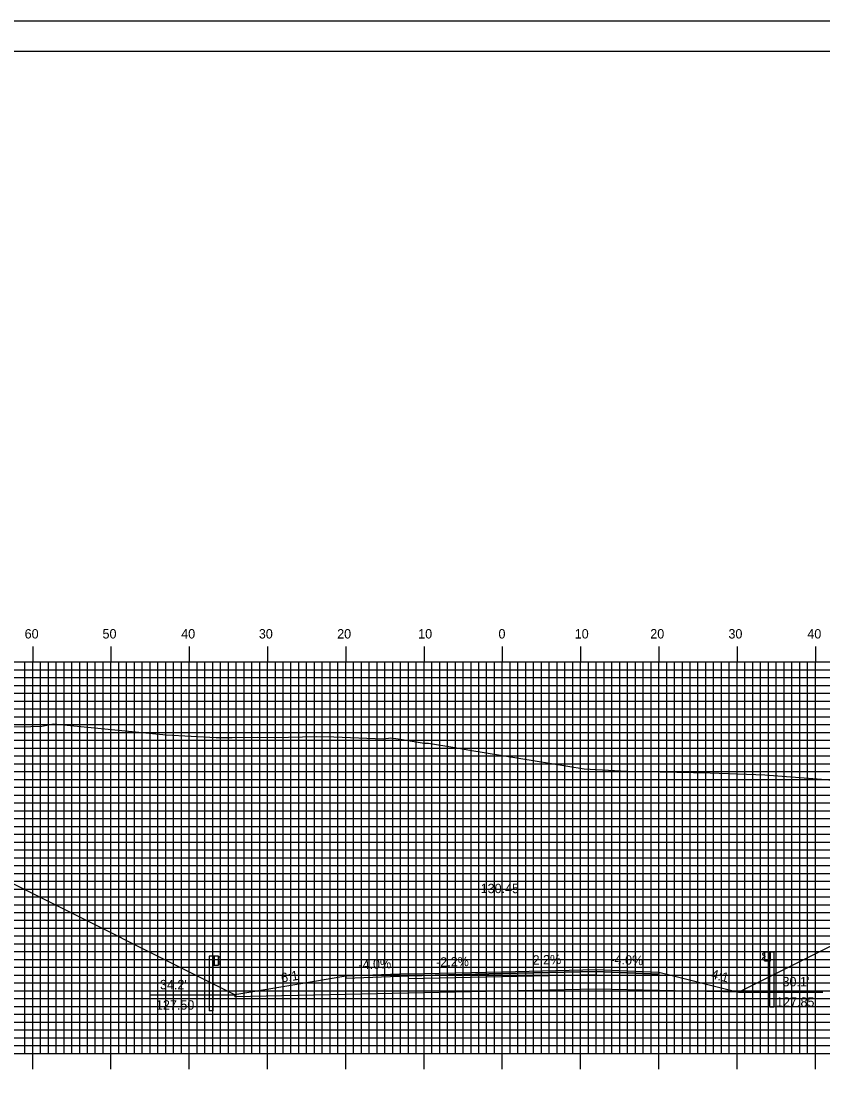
# Model space of a CAD drawing. Extents: x 1785008 to 1785352, y 442591 to 442811.
# Drawn here: x 1785112.5 to 1785215, y 442676.2 to 442810.5 of the extents above; entities that cross this region are included whole.
import ezdxf

# ---------------------------------------------------------------- set-up
doc = ezdxf.new("R2010")
doc.units = 0
for name, color, linetype in [('ANNOTATION', 7, 'Continuous'), ('BORDER', 7, 'Continuous'), ('D_Guardrail_Beam_Lt', 7, 'Continuous'), ('D_Guardrail_Beam_Rt', 7, 'Continuous'), ('D_Roadway_Centerline', 7, 'Continuous'), ('D_Roadway_Centerline_Text', 7, 'Continuous'), ('D_Roadway_Edge_Shoulder', 7, 'Continuous'), ('D_Roadway_Edge_TW', 7, 'Continuous'), ('D_Roadway_Pavement', 7, 'Continuous'), ('D_Roadway_SlopeLines', 7, 'Continuous'), ('D_Roadway_SubGrade', 7, 'Continuous'), ('H_V ANNOTATION', 7, 'Continuous'), ('MAJOR', 7, 'Continuous'), ('MINOR', 7, 'Continuous'), ('PDRAIN', 7, 'Continuous'), ('PLOT BOUNDARY', 7, 'Continuous'), ('S_Roadway_Centerline', 7, 'Continuous')]:
    doc.layers.add(name, color=color, linetype=linetype)

msp = doc.modelspace()

# ---------------------------------------------------------------- linework, layer by layer
at = {"layer": 'BORDER'}
msp.add_lwpolyline([(1785024.43, 442596.67), (1785344.43, 442596.67), (1785344.43, 442806.67), (1785024.43, 442806.67)], close=True, dxfattribs=at)
at = {"layer": 'D_Guardrail_Beam_Lt'}
for p, q in [((1785136.59, 442691.11), (1785136.59, 442684.11)), ((1785137.06, 442691.11), (1785136.59, 442691.11)), ((1785137.75, 442691.11), (1785137.06, 442691.11)), ((1785137.06, 442691.11), (1785137.06, 442689.94)), ((1785137.12, 442691.11), (1785137.12, 442689.94)), ((1785137.23, 442691.11), (1785137.23, 442689.94)), ((1785137.75, 442689.94), (1785137.75, 442691.11)), ((1785137.75, 442691.03), (1785137.82, 442691.01)), ((1785137.84, 442691.01), (1785137.98, 442690.91)), ((1785137.06, 442689.94), (1785137.75, 442689.94)), ((1785137.08, 442684.11), (1785137.08, 442689.94)), ((1785137.75, 442690.56), (1785137.75, 442690.49)), ((1785137.82, 442690.04), (1785137.75, 442690.03)), ((1785137.98, 442690.76), (1785137.79, 442690.63)), ((1785137.79, 442690.43), (1785137.98, 442690.29)), ((1785137.98, 442690.15), (1785137.84, 442690.05)), ((1785137.08, 442684.11), (1785136.59, 442684.11))]:
    msp.add_line(p, q, dxfattribs=at)
for centre, major_axis, start_param, end_param in [((1785137.81, 442690.97), (0.0417, 0), 0.959931, 1.376053), ((1785137.83, 442690.56), (-0.0789, 0), 5.323254, 6.283185), ((1785137.83, 442690.49), (-0.0789, 0), 6.283185, 7.243116), ((1785137.81, 442690.08), (0.0417, 0), 4.907132, 5.323254), ((1785137.93, 442690.83), (0.0877, 0), 5.323254, 7.243116), ((1785137.93, 442690.22), (0.0877, 0), 5.323254, 7.243116)]:
    msp.add_ellipse(centre, major_axis=major_axis, ratio=0.995501, start_param=start_param, end_param=end_param, dxfattribs=at)
at = {"layer": 'D_Guardrail_Beam_Rt'}
for p, q in [((1785207.47, 442691.53), (1785207.32, 442691.43)), ((1785207.32, 442691.29), (1785207.52, 442691.15)), ((1785207.56, 442691.55), (1785207.48, 442691.54)), ((1785207.55, 442691.09), (1785207.55, 442691.02)), ((1785207.56, 442691.64), (1785208.24, 442691.64)), ((1785207.56, 442690.47), (1785207.56, 442691.64)), ((1785208.08, 442691.64), (1785208.08, 442690.47)), ((1785208.18, 442691.64), (1785208.18, 442690.47)), ((1785208.24, 442691.64), (1785208.71, 442691.64)), ((1785208.24, 442691.64), (1785208.24, 442690.47)), ((1785208.71, 442691.64), (1785208.71, 442684.64)), ((1785207.52, 442690.95), (1785207.32, 442690.82)), ((1785207.32, 442690.68), (1785207.47, 442690.58)), ((1785207.48, 442690.57), (1785207.56, 442690.55)), ((1785208.24, 442690.47), (1785207.56, 442690.47)), ((1785208.22, 442684.64), (1785208.22, 442690.47)), ((1785208.22, 442684.64), (1785208.71, 442684.64))]:
    msp.add_line(p, q, dxfattribs=at)
for centre, major_axis, start_param, end_param in [((1785207.37, 442691.36), (-0.0877, 0), 5.323254, 7.243116), ((1785207.49, 442691.5), (-0.0417, 0), 4.907132, 5.323254), ((1785207.47, 442691.09), (0.0789, 0), 0, 0.959931), ((1785207.47, 442691.02), (0.0789, 0), 5.323254, 6.283185), ((1785207.37, 442690.75), (-0.0877, 0), 5.323254, 7.243116), ((1785207.49, 442690.61), (-0.0417, 0), 0.959931, 1.376053)]:
    msp.add_ellipse(centre, major_axis=major_axis, ratio=0.995501, start_param=start_param, end_param=end_param, dxfattribs=at)
at = {"layer": 'D_Roadway_Edge_Shoulder'}
for points in [[(1785162.03, 442688.85), (1785154.03, 442688.53), (1785154.03, 442688.28), (1785162.03, 442688.6)], [(1785186.03, 442689.37), (1785194.03, 442689.05), (1785194.03, 442688.8), (1785186.03, 442689.12)]]:
    msp.add_lwpolyline(points, close=True, dxfattribs=at)
at = {"layer": 'D_Roadway_Edge_TW'}
msp.add_lwpolyline([(1785162.03, 442688.6), (1785162.03, 442688.85), (1785174.03, 442689.11), (1785186.03, 442689.37), (1785186.03, 442689.12), (1785174.03, 442688.86)], close=True, dxfattribs=at)
at = {"layer": 'D_Roadway_Pavement'}
msp.add_lwpolyline([(1785162.03, 442688.18), (1785162.03, 442688.6), (1785174.03, 442688.86), (1785186.03, 442689.12), (1785186.03, 442688.71), (1785174.03, 442688.44)], close=True, dxfattribs=at)
at = {"layer": 'D_Roadway_SlopeLines'}
for p in [(1785139.85, 442686.16), (1785143.85, 442685.98)]:
    msp.add_line(p, (1785139.85, 442685.9), dxfattribs=at)
for points in [[(1785139.85, 442686.16), (1785082.14, 442715.02), (1785080.89, 442715.56), (1785079.64, 442715.93), (1785078.39, 442716.14), (1785077.14, 442716.18)], [(1785204.2, 442686.51), (1785248.83, 442708.82), (1785250.08, 442709.36), (1785251.33, 442709.73), (1785252.58, 442709.92), (1785253.83, 442709.94)], [(1785154.03, 442688.53), (1785148.03, 442687.53), (1785139.85, 442686.16)], [(1785194.03, 442689.05), (1785204.2, 442686.51)]]:
    msp.add_lwpolyline(points, dxfattribs=at)
at = {"layer": 'D_Roadway_SubGrade'}
msp.add_lwpolyline([(1785154.03, 442688.53), (1785154.03, 442688.28), (1785162.03, 442688.6), (1785174.03, 442688.86), (1785186.03, 442689.12), (1785194.03, 442688.8), (1785194.03, 442689.05), (1785204.2, 442686.51), (1785186.03, 442686.87), (1785174.03, 442686.61), (1785162.03, 442686.35), (1785143.85, 442685.98)], dxfattribs=at)
at = {"layer": 'MAJOR'}
for p, q in [((1785114.03, 442730.67), (1785114.03, 442728.67)), ((1785124.03, 442730.67), (1785124.03, 442728.67)), ((1785134.03, 442730.67), (1785134.03, 442728.67)), ((1785144.03, 442730.67), (1785144.03, 442728.67)), ((1785154.03, 442730.67), (1785154.03, 442728.67)), ((1785164.03, 442730.67), (1785164.03, 442728.67)), ((1785174.03, 442730.67), (1785174.03, 442728.67)), ((1785184.03, 442730.67), (1785184.03, 442728.67)), ((1785194.03, 442730.67), (1785194.03, 442728.67)), ((1785204.03, 442730.67), (1785204.03, 442728.67)), ((1785214.03, 442730.67), (1785214.03, 442728.67)), ((1785034.03, 442728.67), (1785314.03, 442728.67)), ((1785034.03, 442728.67), (1785314.03, 442728.67)), ((1785114.03, 442678.67), (1785114.03, 442728.67)), ((1785124.03, 442678.67), (1785124.03, 442728.67)), ((1785134.03, 442678.67), (1785134.03, 442728.67)), ((1785144.03, 442678.67), (1785144.03, 442728.67)), ((1785154.03, 442678.67), (1785154.03, 442728.67)), ((1785164.03, 442678.67), (1785164.03, 442728.67)), ((1785174.03, 442678.67), (1785174.03, 442728.67)), ((1785184.03, 442678.67), (1785184.03, 442728.67)), ((1785194.03, 442678.67), (1785194.03, 442728.67)), ((1785204.03, 442678.67), (1785204.03, 442728.67)), ((1785214.03, 442678.67), (1785214.03, 442728.67)), ((1785034.03, 442723.67), (1785314.03, 442723.67)), ((1785034.03, 442718.67), (1785314.03, 442718.67)), ((1785034.03, 442713.67), (1785314.03, 442713.67)), ((1785034.03, 442708.67), (1785314.03, 442708.67)), ((1785034.03, 442703.67), (1785314.03, 442703.67)), ((1785034.03, 442698.67), (1785314.03, 442698.67)), ((1785034.03, 442693.67), (1785314.03, 442693.67)), ((1785034.03, 442688.67), (1785314.03, 442688.67)), ((1785034.03, 442683.67), (1785314.03, 442683.67)), ((1785034.03, 442678.67), (1785314.03, 442678.67)), ((1785034.03, 442678.67), (1785314.03, 442678.67)), ((1785114.03, 442676.66), (1785114.03, 442678.67)), ((1785124.03, 442676.66), (1785124.03, 442678.67)), ((1785134.03, 442676.66), (1785134.03, 442678.67)), ((1785144.03, 442676.66), (1785144.03, 442678.67)), ((1785154.03, 442676.66), (1785154.03, 442678.67)), ((1785164.03, 442676.66), (1785164.03, 442678.67)), ((1785174.03, 442676.66), (1785174.03, 442678.67)), ((1785184.03, 442676.66), (1785184.03, 442678.67)), ((1785194.03, 442676.66), (1785194.03, 442678.67)), ((1785204.03, 442676.66), (1785204.03, 442678.67)), ((1785214.03, 442676.66), (1785214.03, 442678.67))]:
    msp.add_line(p, q, dxfattribs=at)
at = {"layer": 'MINOR'}
for p, q in [((1785113.03, 442678.67), (1785113.03, 442728.67)), ((1785115.03, 442678.67), (1785115.03, 442728.67)), ((1785116.03, 442678.67), (1785116.03, 442728.67)), ((1785117.03, 442678.67), (1785117.03, 442728.67)), ((1785118.03, 442678.67), (1785118.03, 442728.67)), ((1785119.03, 442678.67), (1785119.03, 442728.67)), ((1785120.03, 442678.67), (1785120.03, 442728.67)), ((1785121.03, 442678.67), (1785121.03, 442728.67)), ((1785122.03, 442678.67), (1785122.03, 442728.67)), ((1785123.03, 442678.67), (1785123.03, 442728.67)), ((1785125.03, 442678.67), (1785125.03, 442728.67)), ((1785126.03, 442678.67), (1785126.03, 442728.67)), ((1785127.03, 442678.67), (1785127.03, 442728.67)), ((1785128.03, 442678.67), (1785128.03, 442728.67)), ((1785129.03, 442678.67), (1785129.03, 442728.67)), ((1785130.03, 442678.67), (1785130.03, 442728.67)), ((1785131.03, 442678.67), (1785131.03, 442728.67)), ((1785132.03, 442678.67), (1785132.03, 442728.67)), ((1785133.03, 442678.67), (1785133.03, 442728.67)), ((1785135.03, 442678.67), (1785135.03, 442728.67)), ((1785136.03, 442678.67), (1785136.03, 442728.67)), ((1785137.03, 442678.67), (1785137.03, 442728.67)), ((1785138.03, 442678.67), (1785138.03, 442728.67)), ((1785139.03, 442678.67), (1785139.03, 442728.67)), ((1785140.03, 442678.67), (1785140.03, 442728.67)), ((1785141.03, 442678.67), (1785141.03, 442728.67)), ((1785142.03, 442678.67), (1785142.03, 442728.67)), ((1785143.03, 442678.67), (1785143.03, 442728.67)), ((1785145.03, 442678.67), (1785145.03, 442728.67)), ((1785146.03, 442678.67), (1785146.03, 442728.67)), ((1785147.03, 442678.67), (1785147.03, 442728.67)), ((1785148.03, 442678.67), (1785148.03, 442728.67)), ((1785149.03, 442678.67), (1785149.03, 442728.67)), ((1785150.03, 442678.67), (1785150.03, 442728.67)), ((1785151.03, 442678.67), (1785151.03, 442728.67)), ((1785152.03, 442678.67), (1785152.03, 442728.67)), ((1785153.03, 442678.67), (1785153.03, 442728.67)), ((1785155.03, 442678.67), (1785155.03, 442728.67)), ((1785156.03, 442678.67), (1785156.03, 442728.67)), ((1785157.03, 442678.67), (1785157.03, 442728.67)), ((1785158.03, 442678.67), (1785158.03, 442728.67)), ((1785159.03, 442678.67), (1785159.03, 442728.67)), ((1785160.03, 442678.67), (1785160.03, 442728.67)), ((1785161.03, 442678.67), (1785161.03, 442728.67)), ((1785162.03, 442678.67), (1785162.03, 442728.67)), ((1785163.03, 442678.67), (1785163.03, 442728.67)), ((1785165.03, 442678.67), (1785165.03, 442728.67)), ((1785166.03, 442678.67), (1785166.03, 442728.67)), ((1785167.03, 442678.67), (1785167.03, 442728.67)), ((1785168.03, 442678.67), (1785168.03, 442728.67)), ((1785169.03, 442678.67), (1785169.03, 442728.67)), ((1785170.03, 442678.67), (1785170.03, 442728.67)), ((1785171.03, 442678.67), (1785171.03, 442728.67)), ((1785172.03, 442678.67), (1785172.03, 442728.67)), ((1785173.03, 442678.67), (1785173.03, 442728.67)), ((1785175.03, 442678.67), (1785175.03, 442728.67)), ((1785176.03, 442678.67), (1785176.03, 442728.67)), ((1785177.03, 442678.67), (1785177.03, 442728.67)), ((1785178.03, 442678.67), (1785178.03, 442728.67)), ((1785179.03, 442678.67), (1785179.03, 442728.67)), ((1785180.03, 442678.67), (1785180.03, 442728.67)), ((1785181.03, 442678.67), (1785181.03, 442728.67)), ((1785182.03, 442678.67), (1785182.03, 442728.67)), ((1785183.03, 442678.67), (1785183.03, 442728.67)), ((1785185.03, 442678.67), (1785185.03, 442728.67)), ((1785186.03, 442678.67), (1785186.03, 442728.67)), ((1785187.03, 442678.67), (1785187.03, 442728.67)), ((1785188.03, 442678.67), (1785188.03, 442728.67)), ((1785189.03, 442678.67), (1785189.03, 442728.67)), ((1785190.03, 442678.67), (1785190.03, 442728.67)), ((1785191.03, 442678.67), (1785191.03, 442728.67)), ((1785192.03, 442678.67), (1785192.03, 442728.67)), ((1785193.03, 442678.67), (1785193.03, 442728.67)), ((1785195.03, 442678.67), (1785195.03, 442728.67)), ((1785196.03, 442678.67), (1785196.03, 442728.67)), ((1785197.03, 442678.67), (1785197.03, 442728.67)), ((1785198.03, 442678.67), (1785198.03, 442728.67)), ((1785199.03, 442678.67), (1785199.03, 442728.67)), ((1785200.03, 442678.67), (1785200.03, 442728.67)), ((1785201.03, 442678.67), (1785201.03, 442728.67)), ((1785202.03, 442678.67), (1785202.03, 442728.67)), ((1785203.03, 442678.67), (1785203.03, 442728.67)), ((1785205.03, 442678.67), (1785205.03, 442728.67)), ((1785206.03, 442678.67), (1785206.03, 442728.67)), ((1785207.03, 442678.67), (1785207.03, 442728.67)), ((1785208.03, 442678.67), (1785208.03, 442728.67)), ((1785209.03, 442678.67), (1785209.03, 442728.67)), ((1785210.03, 442678.67), (1785210.03, 442728.67)), ((1785211.03, 442678.67), (1785211.03, 442728.67)), ((1785212.03, 442678.67), (1785212.03, 442728.67)), ((1785213.03, 442678.67), (1785213.03, 442728.67)), ((1785034.03, 442727.67), (1785314.03, 442727.67)), ((1785034.03, 442726.67), (1785314.03, 442726.67)), ((1785034.03, 442725.67), (1785314.03, 442725.67)), ((1785034.03, 442724.67), (1785314.03, 442724.67)), ((1785034.03, 442722.67), (1785314.03, 442722.67)), ((1785034.03, 442721.67), (1785314.03, 442721.67)), ((1785034.03, 442720.67), (1785314.03, 442720.67)), ((1785034.03, 442719.67), (1785314.03, 442719.67)), ((1785034.03, 442717.67), (1785314.03, 442717.67)), ((1785034.03, 442716.67), (1785314.03, 442716.67)), ((1785034.03, 442715.67), (1785314.03, 442715.67)), ((1785034.03, 442714.67), (1785314.03, 442714.67)), ((1785034.03, 442712.67), (1785314.03, 442712.67)), ((1785034.03, 442711.67), (1785314.03, 442711.67)), ((1785034.03, 442710.67), (1785314.03, 442710.67)), ((1785034.03, 442709.67), (1785314.03, 442709.67)), ((1785034.03, 442707.67), (1785314.03, 442707.67)), ((1785034.03, 442706.67), (1785314.03, 442706.67)), ((1785034.03, 442705.67), (1785314.03, 442705.67)), ((1785034.03, 442704.67), (1785314.03, 442704.67)), ((1785034.03, 442702.67), (1785314.03, 442702.67)), ((1785034.03, 442701.67), (1785314.03, 442701.67)), ((1785034.03, 442700.67), (1785314.03, 442700.67)), ((1785034.03, 442699.67), (1785314.03, 442699.67)), ((1785034.03, 442697.67), (1785314.03, 442697.67)), ((1785034.03, 442696.67), (1785314.03, 442696.67)), ((1785034.03, 442695.67), (1785314.03, 442695.67)), ((1785034.03, 442694.67), (1785314.03, 442694.67)), ((1785034.03, 442692.67), (1785314.03, 442692.67)), ((1785034.03, 442691.67), (1785314.03, 442691.67)), ((1785034.03, 442690.67), (1785314.03, 442690.67)), ((1785034.03, 442689.67), (1785314.03, 442689.67)), ((1785034.03, 442687.67), (1785314.03, 442687.67)), ((1785034.03, 442686.67), (1785314.03, 442686.67)), ((1785034.03, 442685.67), (1785314.03, 442685.67)), ((1785034.03, 442684.67), (1785314.03, 442684.67)), ((1785034.03, 442682.67), (1785314.03, 442682.67)), ((1785034.03, 442681.67), (1785314.03, 442681.67)), ((1785034.03, 442680.67), (1785314.03, 442680.67)), ((1785034.03, 442679.67), (1785314.03, 442679.67))]:
    msp.add_line(p, q, dxfattribs=at)
at = {"layer": 'PDRAIN'}
for p, q in [((1785129.13, 442686.16), (1785139.85, 442686.16)), ((1785204.2, 442686.51), (1785214.97, 442686.51))]:
    msp.add_line(p, q, dxfattribs=at)
at = {"layer": 'PLOT BOUNDARY'}
msp.add_lwpolyline([(1785008.24, 442590.55), (1785348.24, 442590.55), (1785348.24, 442810.55), (1785008.24, 442810.55)], close=True, dxfattribs=at)
at = {"layer": 'S_Roadway_Centerline'}
msp.add_lwpolyline([(1785108.74, 442720.4), (1785113.79, 442720.45), (1785115.18, 442720.48), (1785116.7, 442720.79), (1785131.09, 442719.35), (1785137.49, 442719.02), (1785137.96, 442719.04), (1785139.53, 442719.02), (1785142.78, 442719.06), (1785144.9, 442719.02), (1785150.34, 442719.15), (1785152.49, 442719.11), (1785158.84, 442718.85), (1785159.79, 442718.97), (1785160.71, 442718.85), (1785164.03, 442718.32), (1785164.61, 442718.28), (1785167.71, 442717.79), (1785169.9, 442717.39), (1785184.47, 442715.02), (1785189.94, 442714.74), (1785200.6, 442714.51), (1785207.59, 442714.24), (1785214.79, 442713.7), (1785218.96, 442713.3)], dxfattribs=at)

# ---------------------------------------------------------------- texts
at = {"layer": 'ANNOTATION'}
for s, rotation, p in [('-2.2%', 1.2603, (1785165.58, 442689.73)), ('2.2%', 1.2603, (1785177.91, 442690)), ('-4.0%', 357.7094, (1785187.82, 442690.1)), ('-4.0%', 2.2906, (1785155.66, 442689.39)), ('6:1', 9.4623, (1785145.86, 442687.71)), ('4:1', 345.9638, (1785200.62, 442688.27))]:
    msp.add_text(s, height=1.2, rotation=rotation, dxfattribs=at).set_placement(p)
for s, p in [("30.1'", (1785209.83, 442687.24)), ("34.2'", (1785130.29, 442686.86)), ('127.85', (1785209, 442684.64)), ('127.50', (1785129.77, 442684.26))]:
    msp.add_text(s, height=1.2, dxfattribs=at).set_placement(p)
at = {"layer": 'D_Roadway_Centerline'}
for s, p in [('C', (1785174.02, 442689.11)), ('L', (1785174.03, 442689.1))]:
    msp.add_text(s, height=0.0146, dxfattribs=at).set_placement(p)
at = {"layer": 'D_Roadway_Centerline_Text'}
msp.add_text('130.45', height=1.2, dxfattribs=at).set_placement((1785171.26, 442699.14))
at = {"layer": 'H_V ANNOTATION'}
for s, p in [('60', (1785113, 442731.67)), ('50', (1785122.95, 442731.67)), ('40', (1785133, 442731.67)), ('30', (1785142.92, 442731.67)), ('20', (1785152.93, 442731.67)), ('10', (1785163.28, 442731.67)), ('0', (1785173.54, 442731.67)), ('10', (1785183.28, 442731.67)), ('20', (1785192.93, 442731.67)), ('30', (1785202.92, 442731.67)), ('40', (1785213, 442731.67))]:
    msp.add_text(s, height=1.2, dxfattribs=at).set_placement(p)

doc.saveas('drawing.dxf')
